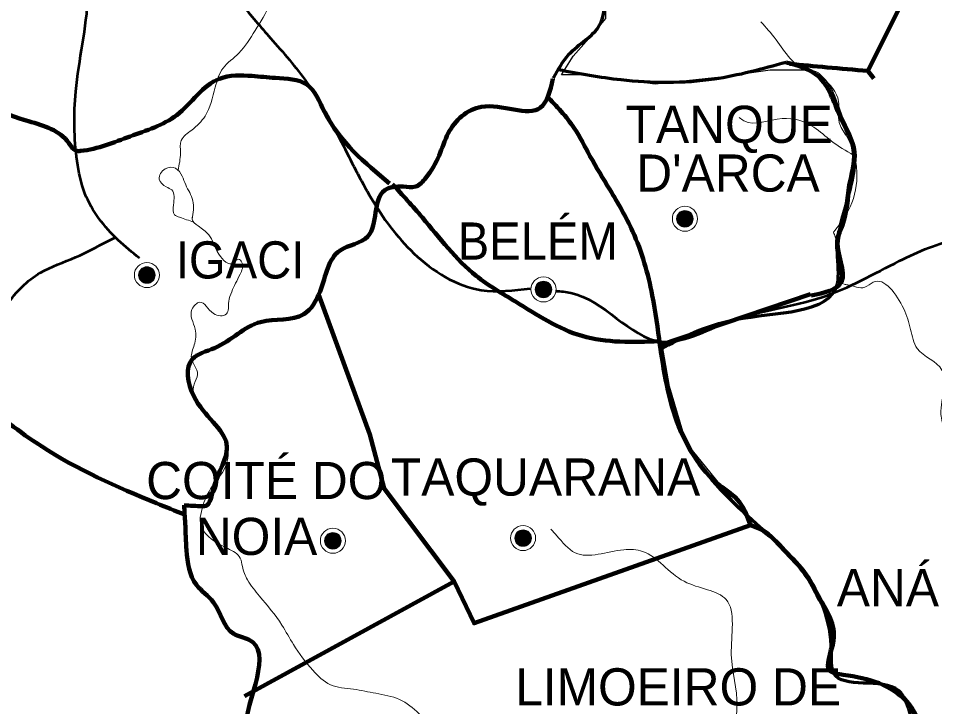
# Model space of a CAD drawing. Extents: x 512883 to 1063249, y 8784064 to 9081064.
# Drawn here: x 755485 to 792467, y 8924405 to 8952193 of the extents above; entities that cross this region are included whole.
import ezdxf

# ---------------------------------------------------------------- set-up
doc = ezdxf.new("R2010")
doc.units = 0
doc.header["$LTSCALE"] = 600
for name, color, linetype, lineweight in [('10', 7, 'Continuous', 53), ('13', 7, 'Continuous', 90), ('20', 7, 'Continuous', 53), ('4', 7, 'Continuous', 13), ('5', 7, 'Continuous', 13), ('60', 7, 'Continuous', 25), ('7', 7, 'Continuous', 13)]:
    doc.layers.add(name, color=color, linetype=linetype, lineweight=lineweight)

msp = doc.modelspace()

# ---------------------------------------------------------------- linework, layer by layer
at = {"layer": '10'}
for points in [[(760373.1, 8942504.5), (759520.9, 8943232.2), (758173.4, 8945126.8), (757857.6, 8946419.7), (757806.3, 8949236.7), (758306.2, 8953099), (758380.2, 8955499.1), (758834.8, 8958004.7), (759126.7, 8959859.4)], [(753024.3, 8928810.8), (754028, 8932114.6), (753933.5, 8935630), (753912.2, 8937835.1), (755033.7, 8940646.8), (756371.5, 8941919.9), (757796.1, 8942548.3), (759099.7, 8943197.1), (759414.7, 8943351.8)]]:
    msp.add_spline(points, degree=3, dxfattribs=at)
at = {"layer": '13', "lineweight": 25}
msp.add_line((785124.3, 8931749.4), (782699.4, 8934746.6), dxfattribs=at)
at = {"layer": '13'}
msp.add_line((773079.1, 8929461.1), (764606.8, 8924822.3), dxfattribs=at)
for points in [[(790399.5, 8968972.9), (790656.5, 8968416.5), (789880.2, 8962278.7), (789119.1, 8960231.1), (790366.5, 8958294.4), (790875.4, 8957711.7), (791390.8, 8956544.8), (791681.4, 8953895.4), (789774.1, 8950070.4), (790016.3, 8949759.2)], [(785032.8, 8931732.7), (773881.6, 8927773.4), (773079.1, 8929461.1), (770243.9, 8933208.3), (769677, 8935397.6), (767593.6, 8941051.2)], [(787449.8, 8941056.1), (781374.7, 8939003.9), (781674.8, 8937314.5), (782217.5, 8935500.7), (782607.8, 8934729.8)]]:
    msp.add_lwpolyline(points, dxfattribs=at)
at = {"layer": '13', "lineweight": 25}
for points in [[(787332.9, 8950099.2), (785823.8, 8950099.2), (783836.6, 8949815), (781186.9, 8949530.8), (779767.4, 8949720.3), (778537.2, 8949909.7), (777401.6, 8949909.7), (777874.8, 8950667.6), (778726.4, 8951614.9), (779199.6, 8952183.3), (779199.6, 8953699), (779294.2, 8955404.1), (779294.2, 8957014.5), (778726.4, 8958340.8), (777685.5, 8959761.7), (775982.1, 8960519.6), (774184.1, 8961656.3), (773237.8, 8962698.4), (772102.2, 8962982.6), (770020.3, 8964971.9), (768316.9, 8966298.1), (767276, 8967624.4), (766531.3, 8968098.7)], [(782699.4, 8934746.6), (782309, 8935517.4), (781766.3, 8937331.2), (781466.3, 8939020.6), (787541.4, 8941072.8), (787576.4, 8941019.1)]]:
    msp.add_lwpolyline(points, dxfattribs=at)
at = {"layer": '13', "lineweight": 70}
for points in [[(777083.3, 8949780.2), (777094.8, 8949799.9), (777707.5, 8950740.9), (778940.6, 8951913.5), (779169.6, 8953020.3), (779097.1, 8954126.1), (779053.8, 8954397.2)], [(786474.1, 8950414.5), (783567.3, 8949737.3), (779809.2, 8949704.3), (777285.7, 8950110.8)]]:
    msp.add_spline(points, degree=3, dxfattribs=at)
at = {"layer": '13'}
for points in [[(751215.9, 8950362.8), (753762, 8949641), (753762.7, 8949578.4), (755890.1, 8948041), (757527.9, 8947149), (757853, 8946837), (757993.7, 8946837.5), (759997, 8947428.2), (761876.7, 8948289.9), (763609.1, 8949756.3), (764914.3, 8949864.8), (765859.8, 8949784.4), (767129, 8949517.2), (767844.7, 8948413.5), (770470.8, 8945520.4)], [(787484.9, 8941002.4), (788682.8, 8941531.7), (788542.6, 8943305), (788717.9, 8943806.4), (789021.2, 8945456), (789207.5, 8946792.2), (788648.9, 8948230.3), (787766.7, 8949855.2), (786474.1, 8950414.5)], [(786606.8, 8950357.1), (788124.5, 8950211.1), (789774.1, 8950070.4)], [(762172.1, 8932529), (762915.7, 8932495.9), (762996.1, 8932496.2), (763331.1, 8933102.5), (763892.9, 8935003.3), (762565.1, 8936939.8), (762508.3, 8938442.1), (763407.8, 8938883.2), (765265.4, 8939932.7), (767010.5, 8940251.3), (767663.5, 8941171.6), (768469.3, 8942822.8), (769588.6, 8943389.9), (770271.4, 8945249.4), (771013.5, 8945397.9), (771515.9, 8945399.5), (771934, 8945755.6), (772466.8, 8946654.7), (772838.7, 8947553.2), (774173.5, 8948621.8), (776565.6, 8948587.8), (777063.2, 8949744.4)], [(781374.7, 8939003.9), (781071.2, 8941006.3), (780278.8, 8943591.4), (779355.7, 8945278.7), (778556.9, 8946632.6), (777921.4, 8947757.4), (776806.7, 8949056.3)], [(781351.7, 8939155.6), (778235.3, 8939369.4), (775546.8, 8940758.9), (773967.6, 8941797.2), (771791, 8944148.3), (770590.2, 8945500.8)], [(753891, 8936795.6), (756417.2, 8934916.6), (761065.3, 8932615.2), (762196.6, 8932157.8)], [(785040.3, 8931729.6), (784498.7, 8932774.3), (783687.6, 8933418.6), (782607.8, 8934729.8)], [(766028.8, 8920178.8), (764599.9, 8923358.2), (764775.8, 8927112.7), (764178.7, 8927345.5), (763360.7, 8928615.9), (762669.5, 8929323.2), (762272.1, 8930720.1), (762219.9, 8931805), (762171.7, 8932535.3)], [(792238.3, 8921764.6), (791300.4, 8924639.2), (788779.9, 8925695.1), (788253.5, 8925837.3), (788360.7, 8927048), (787798.9, 8928778.3), (787245.4, 8929757.3), (786370.3, 8930735.3), (785436.6, 8931567), (785032.8, 8931732.7)]]:
    msp.add_spline(points, degree=3, dxfattribs=at)
at = {"layer": '13', "lineweight": 25}
for points in [[(787576.4, 8941019.1), (788774.3, 8941548.4), (788634.1, 8943321.8), (788809.5, 8943823.2), (789112.8, 8945472.7), (789299, 8946808.9), (788740.4, 8948247), (787858.2, 8949871.9), (787332.9, 8950099.2)], [(792329.9, 8921781.3), (791392, 8924655.9), (788871.4, 8925711.8), (788345, 8925854), (788452.2, 8927064.7), (787890.4, 8928795), (787336.9, 8929774), (786461.8, 8930752), (785528.1, 8931583.7), (785124.3, 8931749.4)]]:
    msp.add_spline(points, degree=3, dxfattribs=at)
at = {"layer": '20'}
for points in [[(762022.2, 8956228.6), (763065.5, 8954766.9), (764487.8, 8952789.5), (765663, 8951394.6), (767135.2, 8949600.3), (768531.3, 8947190.8), (769724.3, 8944935.2), (771450.3, 8942705.1), (774169.2, 8941219.5), (776144.1, 8941290.1)], [(777166.8, 8941184.2), (777784, 8941113.6), (781400.4, 8939142.2), (784141.8, 8939936.8), (787923.8, 8940936.4), (791046, 8942397.5), (793482.7, 8943294.7), (796021, 8942961.4), (797391.7, 8941602.9), (801402.2, 8942320.6), (803686.7, 8944268.7), (805438.1, 8945832.3), (806707.2, 8947652.2), (808027.2, 8948651.9), (817723.4, 8947344.6), (820490.2, 8947549.7), (822317.8, 8947447.2), (823942.3, 8946575.7), (825211.4, 8945755.4), (827474, 8943741.2), (830718.6, 8937881.3)]]:
    msp.add_spline(points, degree=3, dxfattribs=at)
at = {"layer": '4', "lineweight": 70}
for points in [[(781383.8, 8938829.6), (784412.3, 8940030), (788542.7, 8941469.8), (788543.9, 8942727.5), (788863.5, 8944569), (789201.8, 8946908.8), (788671.4, 8948289.4), (787820.1, 8949815.2), (786474.1, 8950414.5)], [(792238.3, 8921764.6), (791503.1, 8924017.9), (791016, 8925049.1), (788389.3, 8925758.2), (788303.5, 8926642.7), (787188.2, 8929831.3), (784783.9, 8932224.2), (782217.5, 8935500.7), (781373.7, 8938939.8)]]:
    msp.add_spline(points, degree=3, dxfattribs=at)
at = {"layer": '4'}
msp.add_spline([(790626.6, 8917060.2), (788215.9, 8921467.3), (786280.8, 8922658.5), (784541.4, 8923024.9), (784488.7, 8924403.8), (784259.8, 8926504.5), (784051.5, 8928728.3), (782354.1, 8929464.7), (780679.3, 8930673.9), (779919.1, 8930742.9), (777956.9, 8930617.7), (777220, 8931303.7), (776981.3, 8931573.4)], degree=3, dxfattribs=at)
at = {"layer": '5'}
for p, q in [((782060.8, 8944169.5), (782711.8, 8944169.5)), ((782068.9, 8944199.5), (782703.7, 8944199.5)), ((782079.7, 8944229.5), (782692.9, 8944229.8)), ((782094.1, 8944259.5), (782678.8, 8944259.5)), ((782112.4, 8944289.5), (782660.5, 8944289.5)), ((782136.4, 8944319.5), (782636.8, 8944319.5)), ((782165.5, 8944349.5), (782607.1, 8944349.5)), ((782205.1, 8944379.5), (782567.5, 8944379.5)), ((782262.4, 8944409.5), (782510.2, 8944409.5)), ((782053.9, 8944109.5), (782718.7, 8944109.5)), ((782054.5, 8944079.5), (782718.4, 8944079.5)), ((782056, 8944139.5), (782716.6, 8944139.5)), ((782057.5, 8944049.5), (782715.1, 8944049.5)), ((782063.5, 8944019.5), (782709.1, 8944019.5)), ((782072.5, 8943989.5), (782700.1, 8943989.5)), ((782085.1, 8943959.5), (782687.8, 8943959.8)), ((782101, 8943929.5), (782671.6, 8943929.5)), ((782121.7, 8943899.5), (782651.2, 8943899.8)), ((782146.9, 8943869.2), (782626, 8943869.5)), ((782180.2, 8943839.5), (782592.4, 8943839.5)), ((782225.2, 8943809.5), (782547.4, 8943809.5)), ((782299, 8943779.5), (782473.3, 8943779.5)), ((760366.8, 8941956.9), (760980, 8941957.2)), ((760381.2, 8941986.9), (760965.9, 8941986.9)), ((760399.5, 8942016.9), (760947.6, 8942016.9)), ((760423.5, 8942046.9), (760923.9, 8942046.9)), ((760452.6, 8942076.9), (760894.2, 8942076.9)), ((760492.2, 8942106.9), (760854.6, 8942106.9)), ((760549.5, 8942136.9), (760797.3, 8942136.9)), ((760341, 8941836.9), (761005.8, 8941836.9)), ((760341.6, 8941806.9), (761005.5, 8941806.9)), ((760343.1, 8941866.9), (761003.7, 8941866.9)), ((760344.6, 8941776.9), (761002.2, 8941776.9)), ((760347.9, 8941896.9), (760998.9, 8941896.9)), ((760350.6, 8941746.9), (760996.2, 8941746.9)), ((760356, 8941926.9), (760990.8, 8941926.9)), ((760359.6, 8941716.9), (760987.2, 8941716.9)), ((760372.2, 8941686.9), (760974.9, 8941687.2)), ((760388.1, 8941656.9), (760958.7, 8941656.9)), ((760408.8, 8941626.9), (760938.3, 8941627.2)), ((760434, 8941596.6), (760913.1, 8941596.9)), ((760467.3, 8941566.9), (760879.5, 8941566.9)), ((760512.3, 8941536.9), (760834.5, 8941536.9)), ((760586.1, 8941506.9), (760760.4, 8941506.9)), ((776347.7, 8941257), (777012.5, 8941257)), ((776348.3, 8941227), (777012.2, 8941227)), ((776349.8, 8941287), (777010.4, 8941287)), ((776351.3, 8941197), (777008.9, 8941197)), ((776354.6, 8941317), (777005.6, 8941317)), ((776362.7, 8941347), (776997.5, 8941347)), ((776373.5, 8941377), (776986.7, 8941377.3)), ((776387.9, 8941407), (776972.6, 8941407)), ((776406.2, 8941437), (776954.3, 8941437)), ((776430.2, 8941467), (776930.6, 8941467)), ((776459.3, 8941497), (776900.9, 8941497)), ((776498.9, 8941527), (776861.3, 8941527)), ((776556.2, 8941557), (776804, 8941557)), ((776357.3, 8941167), (777002.9, 8941167)), ((776366.3, 8941137), (776993.9, 8941137)), ((776378.9, 8941107), (776981.6, 8941107.3)), ((776394.8, 8941077), (776965.4, 8941077)), ((776415.5, 8941047), (776945, 8941047.3)), ((776440.7, 8941016.7), (776919.8, 8941017)), ((776474, 8940987), (776886.2, 8940987)), ((776519, 8940957), (776841.2, 8940957)), ((776592.8, 8940927), (776767.1, 8940927)), ((767873.3, 8931231.4), (768486.5, 8931231.7)), ((767887.7, 8931261.4), (768472.4, 8931261.4)), ((767906, 8931291.4), (768454.1, 8931291.4)), ((767930, 8931321.4), (768430.4, 8931321.4)), ((767959.1, 8931351.4), (768400.7, 8931351.4)), ((767998.7, 8931381.4), (768361.1, 8931381.4)), ((768056, 8931411.4), (768303.8, 8931411.4)), ((775524, 8931219.7), (776188.8, 8931219.7)), ((775526.1, 8931249.7), (776186.7, 8931249.7)), ((775530.9, 8931279.7), (776181.9, 8931279.7)), ((775539, 8931309.7), (776173.8, 8931309.7)), ((775549.8, 8931339.7), (776163, 8931340)), ((775564.2, 8931369.7), (776148.9, 8931369.7)), ((775582.5, 8931399.7), (776130.6, 8931399.7)), ((775606.5, 8931429.7), (776106.9, 8931429.7)), ((775635.6, 8931459.7), (776077.2, 8931459.7)), ((775675.2, 8931489.7), (776037.6, 8931489.7)), ((775732.5, 8931519.7), (775980.3, 8931519.7)), ((767847.5, 8931111.4), (768512.3, 8931111.4)), ((767848.1, 8931081.4), (768512, 8931081.4)), ((767849.6, 8931141.4), (768510.2, 8931141.4)), ((767851.1, 8931051.4), (768508.7, 8931051.4)), ((767854.4, 8931171.4), (768505.4, 8931171.4)), ((767857.1, 8931021.4), (768502.7, 8931021.4)), ((767862.5, 8931201.4), (768497.3, 8931201.4)), ((767866.1, 8930991.4), (768493.7, 8930991.4)), ((767878.7, 8930961.4), (768481.4, 8930961.7)), ((767894.6, 8930931.4), (768465.2, 8930931.4)), ((767915.3, 8930901.4), (768444.8, 8930901.7)), ((767940.5, 8930871.1), (768419.6, 8930871.4)), ((767973.8, 8930841.4), (768386, 8930841.4)), ((775524.6, 8931189.7), (776188.5, 8931189.7)), ((775527.6, 8931159.7), (776185.2, 8931159.7)), ((775533.6, 8931129.7), (776179.2, 8931129.7)), ((775542.6, 8931099.7), (776170.2, 8931099.7)), ((775555.2, 8931069.7), (776157.9, 8931070)), ((775571.1, 8931039.7), (776141.7, 8931039.7)), ((775591.8, 8931009.7), (776121.3, 8931010)), ((775617, 8930979.4), (776096.1, 8930979.7)), ((775650.3, 8930949.7), (776062.5, 8930949.7)), ((775695.3, 8930919.7), (776017.5, 8930919.7)), ((775769.1, 8930889.7), (775943.4, 8930889.7)), ((768018.8, 8930811.4), (768341, 8930811.4)), ((768092.6, 8930781.4), (768266.9, 8930781.4))]:
    msp.add_line(p, q, dxfattribs=at)
for centre, radius in [((782386.4, 8944100.5), 506.1), ((782386.4, 8944100.5), 332.9), ((760673.5, 8941827.9), 506.1), ((760673.5, 8941827.9), 332.9), ((776680.2, 8941248), 506.1), ((776680.2, 8941248), 332.9), ((768180, 8931102.4), 506.1), ((775856.5, 8931210.7), 506.1), ((768180, 8931102.4), 332.9), ((775856.5, 8931210.7), 332.9)]:
    msp.add_circle(centre, radius, dxfattribs=at)
at = {"layer": '60', "lineweight": 13}
msp.add_line((762549, 8943966.5), (762496.7, 8944081.9), dxfattribs=at)
at = {"layer": '60'}
msp.add_spline([(928828.8, 9027989.5), (927727.3, 9017705.9), (905698.2, 8975836.8), (863108.4, 8926255), (823455.9, 8876673.2), (798489.5, 8846556.8), (787107.7, 8828193.2)], degree=3, dxfattribs=at)
msp.add_spline([(928828.8, 9027989.5), (927727.3, 9017705.9), (905698.2, 8975836.8), (863108.4, 8926255), (823455.9, 8876673.2), (798489.5, 8846556.8), (787107.7, 8828193.2)], degree=3, dxfattribs=at)
at = {"layer": '60', "lineweight": 13}
for points in [[(761930.5, 8946052.6), (762027.4, 8946763.3), (762062.9, 8947262.6), (762482.1, 8947680), (763020.7, 8948243.3), (763432.6, 8949409.5), (763747.6, 8950180.1), (764386.5, 8950785.3), (765042.7, 8951702.7), (765596.6, 8952765.3), (765524.3, 8953992.4), (765108.6, 8955301.8), (765198.3, 8956446.2), (765294.1, 8956966.6)], [(788382.4, 8943559.9), (788892.7, 8944265.1), (789322.9, 8945618.6), (789296.2, 8946305), (788902.2, 8947447.9), (788614.9, 8947987.9), (788586.5, 8948840.8), (787952.4, 8949816.6), (787668.1, 8950044.6), (787365.2, 8950106), (786063.8, 8951329.5), (785452.2, 8952055.7)], [(789195.2, 8946661.8), (788299.8, 8947238.1), (787589.1, 8947797.6), (786316.2, 8948147.4), (784765.4, 8948059.5), (784582.8, 8948183.8)], [(762496.7, 8944081.9), (762529.7, 8944830.1), (762241.4, 8945474.1), (762096.9, 8945827.3), (761832, 8946138.6), (761409, 8946116.5), (761171.2, 8945699.7), (761456.3, 8945388.6), (761679.2, 8945264.4), (761745.5, 8944661.3), (761789.6, 8944266.2), (761992.1, 8944162.8), (762549, 8943966.5)], [(763934.9, 8930792.5), (763083.1, 8931351.6), (762836.9, 8931808.5), (762872.6, 8932287.1), (763246.6, 8933203.5), (763842.5, 8934099.8), (763914, 8935036.2), (763564.8, 8935721.6), (763341.4, 8935908.2), (762565.2, 8936987.6), (762581.1, 8937424.5), (762718.4, 8937820.1), (762470.1, 8938485.1), (762586, 8939005.5), (762620.1, 8939650.5), (762491.5, 8940440.6), (762811.1, 8940732.8), (763359.6, 8940276.8), (763883.7, 8940257.6), (763979.7, 8940757.2), (764096.7, 8941152.8), (764432.5, 8941861.1), (764508.4, 8942339.8), (764366.2, 8942464.2), (764166.1, 8942317.9), (763578.3, 8942669.8), (763167.7, 8943459.1), (762741.1, 8943811.4), (762496.7, 8944081.1), (762495.9, 8944164.3)], [(830241.8, 8913061.2), (829149, 8913536.4), (827439.7, 8913177.5), (826147.8, 8913402.5), (825384.3, 8913171.3), (824554.1, 8913584.9), (823759.2, 8914518.6), (822827.3, 8915035.8), (821955, 8915636.5), (821248.5, 8915759.2), (819586.9, 8916711.1), (818533.7, 8917269.5), (817362.3, 8917536.4), (815944.8, 8918260.2), (814975.2, 8918506.9), (813404.4, 8918398.2), (812633.1, 8918978.3), (812224, 8919601.2), (811906.3, 8921202), (811391.5, 8922344.6), (811100.9, 8923217.4), (810271.4, 8923568.6), (809585.4, 8923649.7), (808316.8, 8923562.7), (807869.8, 8923935.8), (806863.7, 8923787.1), (805966.1, 8924928.5), (805085.5, 8926382.1), (804213.4, 8926961.9), (803507.4, 8927043), (803043.7, 8927062.4), (801988.8, 8925707), (801265.4, 8925496.8), (800038, 8925305.8), (799427.5, 8925928.1), (797719, 8927566.3), (796560.5, 8928582.1), (796030.6, 8929204.6), (795985.9, 8929662.2), (795818.1, 8930348.1), (794959.1, 8931656.1), (795129.4, 8932800.8), (795079.4, 8933799.2), (794428.2, 8934462.9), (793375.3, 8934979.8), (792885.7, 8935602.4), (792718.7, 8936205.2), (792849.5, 8937266.5), (792761.8, 8937994.3), (791766, 8938865), (791496.6, 8939633.9), (791206.3, 8940486), (789987, 8941543.2), (789646.5, 8941334.2), (788960.3, 8941436.1), (788819.1, 8941456.5), (788590.6, 8942163.1), (788458, 8943369.2), (788382.4, 8943559.9)], [(810054.4, 8878245.8), (808490.8, 8878441.8), (807059.7, 8878479.1), (805985.9, 8879079.1), (805197, 8879388.8), (804089.5, 8879302.2), (802915.8, 8879818.7), (802471.2, 8879942.2), (801566.7, 8879710.6), (800194.7, 8879893.7), (799198.8, 8880764.4), (798539.4, 8882281), (798171.6, 8882800), (797688, 8882798.5), (797359, 8883484), (796899, 8885209.2), (796928.8, 8886291.1), (797076.8, 8887664.5), (796864.6, 8888766.4), (796120.9, 8890657.2), (796158, 8890990.2), (795488.6, 8891445.8), (794233.1, 8892086.9), (793990.2, 8892190.2), (793056.1, 8892936.3), (792600.3, 8894224.7), (792515.5, 8894661.3), (792310, 8895076.7), (792346.1, 8895513.7), (792422, 8895992.4), (792272.6, 8896865.6), (792611.1, 8897282.7), (793187.8, 8898075), (792840.8, 8898531.6), (792656.5, 8898843.1), (792469.9, 8899383.4), (792192.5, 8900984.4), (791233.7, 8902188), (791205.1, 8903061.7), (790428.6, 8904182.7), (790301.6, 8904806.3), (790202.7, 8906699.1), (789491.8, 8907279.4), (788677.8, 8908109.1), (788165.6, 8908981.2), (787558.3, 8909270.7), (786890.9, 8909518.3), (786443.6, 8909933), (785940.4, 8909869), (785293, 8910137.5), (784748.1, 8910219.1), (784086.8, 8909842.6), (783816.4, 8910715.5), (784068.9, 8911694), (784280.1, 8912776.4), (784271, 8913712.5), (783654.5, 8914958.8), (782986.1, 8915310.4), (782138.8, 8915411.9), (781433.7, 8915388.9), (780682.1, 8916010.8), (780211, 8916799.8), (779683.5, 8917172.7), (779000.8, 8916921), (778497.4, 8916877.9), (777545.7, 8917353.4), (776860.6, 8917351.4), (776253.1, 8917661.6), (776325.9, 8918473.1), (776421.2, 8919035.1), (776035.5, 8919325.1), (775038.5, 8920320.7), (774913.4, 8920757.1), (774003.6, 8921066.4), (773776.3, 8921648.2), (773369.1, 8922083.8), (772780.5, 8922518.9), (772330.2, 8923245.7), (771656.7, 8924117.3), (770865.2, 8924697.4), (769915.8, 8924944.2), (769007.4, 8925107.8), (768078.7, 8925292.3), (767367.8, 8925872.6), (766592, 8926910.4), (766120.9, 8927699.5), (765223, 8928861.7), (764733, 8929525.9), (764526.3, 8930066.2), (764442.5, 8930398.7), (763934.9, 8930792.5)]]:
    msp.add_spline(points, degree=3, dxfattribs=at)
at = {"layer": '7'}
msp.add_line((762549, 8943966.5), (762496.7, 8944081.9), dxfattribs=at)
for points in [[(761930.5, 8946052.6), (762027.4, 8946763.3), (762062.9, 8947262.6), (762482.1, 8947680), (763020.7, 8948243.3), (763432.6, 8949409.5), (763747.6, 8950180.1), (764386.5, 8950785.3), (765042.7, 8951702.7), (765596.6, 8952765.3), (765524.3, 8953992.4), (765108.6, 8955301.8), (765198.3, 8956446.2), (765294.1, 8956966.6)], [(788382.4, 8943559.9), (788892.7, 8944265.1), (789322.9, 8945618.6), (789296.2, 8946305), (788902.2, 8947447.9), (788614.9, 8947987.9), (788586.5, 8948840.8), (787952.4, 8949816.6), (787668.1, 8950044.6), (787365.2, 8950106), (786063.8, 8951329.5), (785452.2, 8952055.7)], [(789195.2, 8946661.8), (788299.8, 8947238.1), (787589.1, 8947797.6), (786316.2, 8948147.4), (784765.4, 8948059.5), (784582.8, 8948183.8)], [(762496.7, 8944081.9), (762529.7, 8944830.1), (762241.4, 8945474.1), (762096.9, 8945827.3), (761832, 8946138.6), (761409, 8946116.5), (761171.2, 8945699.7), (761456.3, 8945388.6), (761679.2, 8945264.4), (761745.5, 8944661.3), (761789.6, 8944266.2), (761992.1, 8944162.8), (762549, 8943966.5)], [(763934.9, 8930792.5), (763083.1, 8931351.6), (762836.9, 8931808.5), (762872.6, 8932287.1), (763246.6, 8933203.5), (763842.5, 8934099.8), (763914, 8935036.2), (763564.8, 8935721.6), (763341.4, 8935908.2), (762565.2, 8936987.6), (762581.1, 8937424.5), (762718.4, 8937820.1), (762470.1, 8938485.1), (762586, 8939005.5), (762620.1, 8939650.5), (762491.5, 8940440.6), (762811.1, 8940732.8), (763359.6, 8940276.8), (763883.7, 8940257.6), (763979.7, 8940757.2), (764096.7, 8941152.8), (764432.5, 8941861.1), (764508.4, 8942339.8), (764366.2, 8942464.2), (764166.1, 8942317.9), (763578.3, 8942669.8), (763167.7, 8943459.1), (762741.1, 8943811.4), (762496.7, 8944081.1), (762495.9, 8944164.3)], [(830241.8, 8913061.2), (829149, 8913536.4), (827439.7, 8913177.5), (826147.8, 8913402.5), (825384.3, 8913171.3), (824554.1, 8913584.9), (823759.2, 8914518.6), (822827.3, 8915035.8), (821955, 8915636.5), (821248.5, 8915759.2), (819586.9, 8916711.1), (818533.7, 8917269.5), (817362.3, 8917536.4), (815944.8, 8918260.2), (814975.2, 8918506.9), (813404.4, 8918398.2), (812633.1, 8918978.3), (812224, 8919601.2), (811906.3, 8921202), (811391.5, 8922344.6), (811100.9, 8923217.4), (810271.4, 8923568.6), (809585.4, 8923649.7), (808316.8, 8923562.7), (807869.8, 8923935.8), (806863.7, 8923787.1), (805966.1, 8924928.5), (805085.5, 8926382.1), (804213.4, 8926961.9), (803507.4, 8927043), (803043.7, 8927062.4), (801988.8, 8925707), (801265.4, 8925496.8), (800038, 8925305.8), (799427.5, 8925928.1), (797719, 8927566.3), (796560.5, 8928582.1), (796030.6, 8929204.6), (795985.9, 8929662.2), (795818.1, 8930348.1), (794959.1, 8931656.1), (795129.4, 8932800.8), (795079.4, 8933799.2), (794428.2, 8934462.9), (793375.3, 8934979.8), (792885.7, 8935602.4), (792718.7, 8936205.2), (792849.5, 8937266.5), (792761.8, 8937994.3), (791766, 8938865), (791496.6, 8939633.9), (791206.3, 8940486), (789987, 8941543.2), (789646.5, 8941334.2), (788960.3, 8941436.1), (788819.1, 8941456.5), (788590.6, 8942163.1), (788458, 8943369.2), (788382.4, 8943559.9)], [(810054.4, 8878245.8), (808490.8, 8878441.8), (807059.7, 8878479.1), (805985.9, 8879079.1), (805197, 8879388.8), (804089.5, 8879302.2), (802915.8, 8879818.7), (802471.2, 8879942.2), (801566.7, 8879710.6), (800194.7, 8879893.7), (799198.8, 8880764.4), (798539.4, 8882281), (798171.6, 8882800), (797688, 8882798.5), (797359, 8883484), (796899, 8885209.2), (796928.8, 8886291.1), (797076.8, 8887664.5), (796864.6, 8888766.4), (796120.9, 8890657.2), (796158, 8890990.2), (795488.6, 8891445.8), (794233.1, 8892086.9), (793990.2, 8892190.2), (793056.1, 8892936.3), (792600.3, 8894224.7), (792515.5, 8894661.3), (792310, 8895076.7), (792346.1, 8895513.7), (792422, 8895992.4), (792272.6, 8896865.6), (792611.1, 8897282.7), (793187.8, 8898075), (792840.8, 8898531.6), (792656.5, 8898843.1), (792469.9, 8899383.4), (792192.5, 8900984.4), (791233.7, 8902188), (791205.1, 8903061.7), (790428.6, 8904182.7), (790301.6, 8904806.3), (790202.7, 8906699.1), (789491.8, 8907279.4), (788677.8, 8908109.1), (788165.6, 8908981.2), (787558.3, 8909270.7), (786890.9, 8909518.3), (786443.6, 8909933), (785940.4, 8909869), (785293, 8910137.5), (784748.1, 8910219.1), (784086.8, 8909842.6), (783816.4, 8910715.5), (784068.9, 8911694), (784280.1, 8912776.4), (784271, 8913712.5), (783654.5, 8914958.8), (782986.1, 8915310.4), (782138.8, 8915411.9), (781433.7, 8915388.9), (780682.1, 8916010.8), (780211, 8916799.8), (779683.5, 8917172.7), (779000.8, 8916921), (778497.4, 8916877.9), (777545.7, 8917353.4), (776860.6, 8917351.4), (776253.1, 8917661.6), (776325.9, 8918473.1), (776421.2, 8919035.1), (776035.5, 8919325.1), (775038.5, 8920320.7), (774913.4, 8920757.1), (774003.6, 8921066.4), (773776.3, 8921648.2), (773369.1, 8922083.8), (772780.5, 8922518.9), (772330.2, 8923245.7), (771656.7, 8924117.3), (770865.2, 8924697.4), (769915.8, 8924944.2), (769007.4, 8925107.8), (768078.7, 8925292.3), (767367.8, 8925872.6), (766592, 8926910.4), (766120.9, 8927699.5), (765223, 8928861.7), (764733, 8929525.9), (764526.3, 8930066.2), (764442.5, 8930398.7), (763934.9, 8930792.5)]]:
    msp.add_spline(points, degree=3, dxfattribs=at)

# ---------------------------------------------------------------- texts
at = {"layer": '5'}
for s, p in [('TANQUE', (779996.1, 8947163.8)), ("D'ARCA", (780423.7, 8945196.1)), ('COITÉ DO', (760643.6, 8932783.7)), ('TAQUARANA', (770522, 8932924.6)), ('NOIA', (762646.2, 8930529)), ('ANÁDIA', (788518.2, 8928456.8)), ('LIMOEIRO DE', (775538, 8924453.8))]:
    msp.add_text(s, height=1500, dxfattribs=at).set_placement(p)
at = {"layer": '5', "width": 0.95}
for s, p in [('BELÉM', (773216, 8942450.8)), ('IGACI', (761842.2, 8941689.9))]:
    msp.add_text(s, height=1500, dxfattribs=at).set_placement(p)

doc.saveas('drawing.dxf')
